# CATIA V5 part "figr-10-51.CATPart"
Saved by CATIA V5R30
Part number: Part1
Bounding box of the stored display mesh (mm): x -68.386 to 32.095, y 0 to 344, z -0.079 to 67.481
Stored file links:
  D:\PROJECTS\CATIA V56R 2020\Resources\Parts File\c10_catia_v5_6r2020_prt\figr-10-51.CATPart
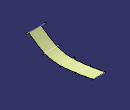
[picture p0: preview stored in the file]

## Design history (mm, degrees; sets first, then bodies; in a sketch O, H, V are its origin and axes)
Body1 (main body)
  Plane1: type Offset, RefPlane zx-plane, Offset 86
  Plane2: type Offset, RefPlane Plane1, Offset 86
  Plane3: type Offset, RefPlane Plane2, Offset 86
  Plane4: type Offset, RefPlane Plane3, Offset 86
  Sketch1 on zx-plane, origin (0, 0, 0), H (-1, 0, 0), V (0, 0, 1)
    line L1 (-32.0954, 67.4806) -> (68.3859, 67.4806)
    horizontal: L1 H
  Sketch2 on Plane1, origin (0, 86, 0), H (-1, 0, 0), V (0, 0, 1)
    line L1 (-24.4409, 14.2252) -> (55.9283, 14.2252)
    horizontal: L1 H
  Sketch3 on Plane2, origin (0, 172, 0), H (-1, 0, 0), V (0, 0, 1)
    line L1 (-24.2042, 0) -> (53.3039, 0)
    point P1 (-24.2042, 0)
    coincidence: P1 H
    horizontal: L1 H
  Sketch4 on Plane3, origin (0, 258, 0), H (-1, 0, 0), V (0, 0, 1)
    line L1 (-23.6533, 8.5985) -> (50.1324, 8.5985)
    horizontal: L1 H
  Sketch5 on Plane4, origin (0, 344, 0), H (-1, 0, 0), V (0, 0, 1)
    line L1 (-20.9465, 23.2339) -> (46.0713, 23.2339)
    horizontal: L1 H
  Sweep1: type Conic, Guide (Sketch1; Sketch2; Sketch3; Sketch4; Sketch5)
